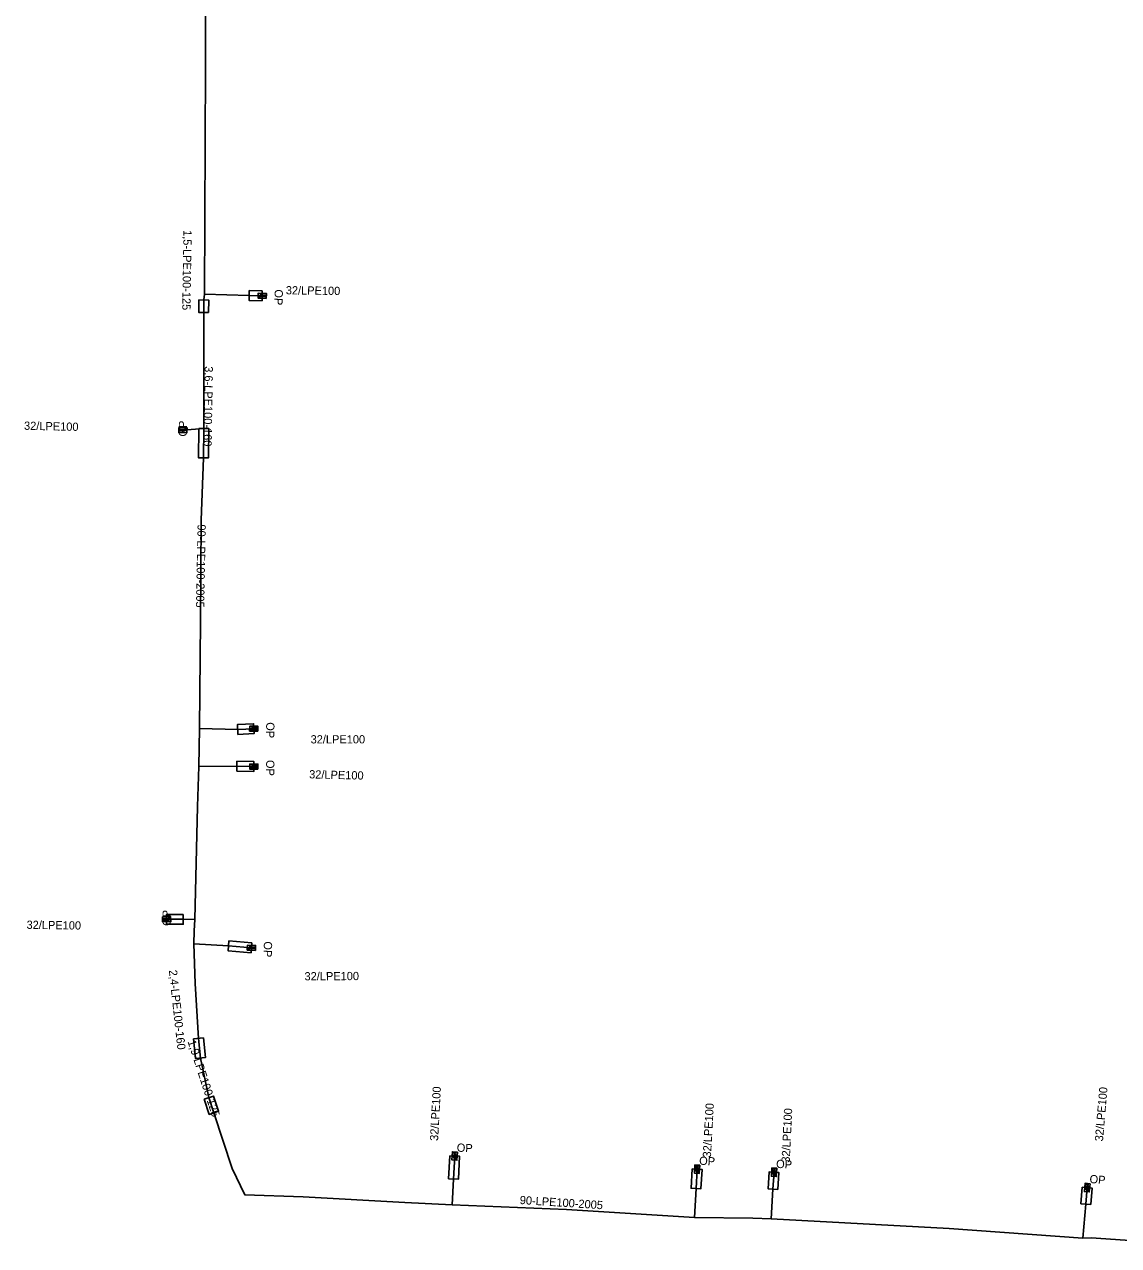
# Model space of a CAD drawing. Extents: x -762921 to -762499, y -1152946 to -1152170.
# Drawn here: x -762776.2 to -762643.3, y -1152901.4 to -1152753 of the extents above; entities that cross this region are included whole.
import ezdxf

# ---------------------------------------------------------------- set-up
doc = ezdxf.new("R2010")
doc.units = 0
for name, color, linetype in [('Vrstva 21', 7, 'Continuous'), ('Vrstva 29', 7, 'Continuous'), ('Vrstva 31', 7, 'Continuous'), ('Vrstva 32', 7, 'Continuous')]:
    doc.layers.add(name, color=color, linetype=linetype)

msp = doc.modelspace()

# ---------------------------------------------------------------- linework, layer by layer
at = {"layer": 'Vrstva 21'}
msp.add_lwpolyline([(-762754.26, -1152739.11), (-762754.22, -1152758.13), (-762754.35, -1152785.8), (-762754.43, -1152786.51), (-762754.45, -1152788.03), (-762754.42, -1152802.11), (-762754.48, -1152805.69), (-762754.74, -1152813.25), (-762754.82, -1152825.57), (-762754.96, -1152838.56), (-762755.02, -1152843.17), (-762755.19, -1152848.05), (-762755.54, -1152861.75), (-762755.6, -1152863.15), (-762755.66, -1152864.72), (-762755.5, -1152869.53), (-762755.09, -1152876.2), (-762754.83, -1152878.59), (-762753.81, -1152883.39), (-762753.21, -1152885.23), (-762751, -1152892), (-762749.45, -1152895.2), (-762742.38, -1152895.45), (-762730.02, -1152896.13), (-762724.27, -1152896.43), (-762710.39, -1152896.96), (-762694.84, -1152897.93), (-762687.76, -1152898.05), (-762685.52, -1152898.12), (-762663.91, -1152899.29), (-762647.65, -1152900.48), (-762646.67, -1152900.42), (-762633.1, -1152901.36)], dxfattribs=at)
at = {"layer": 'Vrstva 29'}
for points in [[(-762747.33, -1152785.4), (-762748.91, -1152785.37), (-762748.93, -1152786.57), (-762747.35, -1152786.6)], [(-762753.85, -1152788.04), (-762753.83, -1152786.52), (-762755.03, -1152786.5), (-762755.05, -1152788.02)], [(-762755.02, -1152802.1), (-762755.08, -1152805.68), (-762753.88, -1152805.7), (-762753.82, -1152802.12)], [(-762750.29, -1152839.28), (-762748.33, -1152839.18), (-762748.39, -1152837.98), (-762750.35, -1152838.08)], [(-762750.43, -1152843.74), (-762748.37, -1152843.78), (-762748.35, -1152842.58), (-762750.41, -1152842.54)], [(-762756.94, -1152861.13), (-762758.95, -1152861.13), (-762758.95, -1152862.33), (-762756.94, -1152862.33)], [(-762748.6, -1152864.59), (-762751.39, -1152864.36), (-762751.49, -1152865.56), (-762748.7, -1152865.79)], [(-762755.69, -1152876.26), (-762755.43, -1152878.65), (-762754.23, -1152878.52), (-762754.49, -1152876.14)], [(-762754.38, -1152883.58), (-762753.78, -1152885.42), (-762752.64, -1152885.04), (-762753.24, -1152883.2)], [(-762724.56, -1152890.45), (-762724.71, -1152893.25), (-762723.51, -1152893.31), (-762723.36, -1152890.51)], [(-762695.12, -1152892.05), (-762695.25, -1152894.4), (-762694.05, -1152894.46), (-762693.92, -1152892.11)], [(-762684.7, -1152894.53), (-762684.57, -1152892.5), (-762685.77, -1152892.42), (-762685.9, -1152894.45)], [(-762647.73, -1152894.27), (-762647.9, -1152896.27), (-762646.7, -1152896.37), (-762646.53, -1152894.37)]]:
    msp.add_lwpolyline(points, close=True, dxfattribs=at)
at = {"layer": 'Vrstva 31'}
for points in [[(-762754.35, -1152785.8), (-762748.92, -1152785.97), (-762747.34, -1152786)], [(-762754.42, -1152802.11), (-762756.98, -1152802.32)], [(-762754.96, -1152838.56), (-762750.32, -1152838.68), (-762748.36, -1152838.58)], [(-762755.02, -1152843.17), (-762750.42, -1152843.14), (-762748.36, -1152843.18)], [(-762755.54, -1152861.75), (-762756.94, -1152861.73), (-762758.95, -1152861.73)], [(-762755.66, -1152864.72), (-762751.44, -1152864.96), (-762748.65, -1152865.19)], [(-762724.27, -1152896.43), (-762724.11, -1152893.28), (-762723.96, -1152890.48)], [(-762694.84, -1152897.93), (-762694.65, -1152894.43), (-762694.52, -1152892.08)], [(-762685.52, -1152898.12), (-762685.3, -1152894.49), (-762685.17, -1152892.46)], [(-762647.65, -1152900.48), (-762647.3, -1152896.32), (-762647.13, -1152894.32)]]:
    msp.add_lwpolyline(points, dxfattribs=at)
at = {"layer": 'Vrstva 32'}
for p, q in [((-762747.536, -1152785.82), (-762747.545, -1152786.17)), ((-762747.137, -1152785.831), (-762747.146, -1152786.18)), ((-762746.941, -1152786.021), (-762747.142, -1152786.015)), ((-762746.945, -1152786.186), (-762746.936, -1152785.836)), ((-762757.375, -1152802.135), (-762757.384, -1152802.485)), ((-762757.379, -1152802.3), (-762757.179, -1152802.305)), ((-762757.183, -1152802.49), (-762757.174, -1152802.141)), ((-762756.784, -1152802.5), (-762756.776, -1152802.151)), ((-762748.558, -1152838.402), (-762748.562, -1152838.752)), ((-762748.159, -1152838.407), (-762748.163, -1152838.757)), ((-762747.96, -1152838.595), (-762748.161, -1152838.592)), ((-762747.962, -1152838.76), (-762747.958, -1152838.41)), ((-762748.56, -1152843.005), (-762748.56, -1152843.355)), ((-762748.161, -1152843.005), (-762748.161, -1152843.355)), ((-762747.96, -1152843.19), (-762748.161, -1152843.19)), ((-762747.96, -1152843.355), (-762747.96, -1152843.005)), ((-762759.356, -1152861.571), (-762759.342, -1152861.921)), ((-762759.35, -1152861.736), (-762759.149, -1152861.728)), ((-762759.141, -1152861.913), (-762759.155, -1152861.563)), ((-762758.743, -1152861.897), (-762758.757, -1152861.547)), ((-762748.846, -1152865.011), (-762748.855, -1152865.36)), ((-762748.447, -1152865.021), (-762748.456, -1152865.37)), ((-762748.255, -1152865.376), (-762748.246, -1152865.026)), ((-762748.251, -1152865.211), (-762748.452, -1152865.206)), ((-762724.124, -1152890.272), (-762723.774, -1152890.292)), ((-762723.763, -1152890.091), (-762724.113, -1152890.071)), ((-762723.928, -1152890.082), (-762723.939, -1152890.282)), ((-762724.146, -1152890.67), (-762723.797, -1152890.69)), ((-762694.321, -1152891.691), (-762694.67, -1152891.67)), ((-762694.486, -1152891.681), (-762694.498, -1152891.882)), ((-762694.707, -1152892.269), (-762694.358, -1152892.29)), ((-762694.683, -1152891.87), (-762694.333, -1152891.892)), ((-762685.355, -1152892.65), (-762685.006, -1152892.669)), ((-762685.334, -1152892.252), (-762684.984, -1152892.271)), ((-762684.973, -1152892.07), (-762685.323, -1152892.051)), ((-762685.138, -1152892.061), (-762685.149, -1152892.262)), ((-762647.322, -1152894.505), (-762646.973, -1152894.535)), ((-762647.287, -1152894.107), (-762646.939, -1152894.137)), ((-762646.922, -1152893.937), (-762647.27, -1152893.907)), ((-762647.086, -1152893.923), (-762647.103, -1152894.123))]:
    msp.add_line(p, q, dxfattribs=at)
for points in [[(-762746.848, -1152786.313), (-762747.848, -1152786.288), (-762747.833, -1152785.688), (-762746.833, -1152785.713), (-762746.848, -1152786.313)], [(-762747.545, -1152786.17), (-762747.675, -1152786.167), (-762747.716, -1152786.149), (-762747.731, -1152786.133), (-762747.744, -1152786.099), (-762747.743, -1152786.049), (-762747.728, -1152786.017), (-762747.712, -1152786.001), (-762747.67, -1152785.985), (-762747.54, -1152785.988)], [(-762747.245, -1152786.178), (-762747.238, -1152785.927), (-762747.251, -1152785.878), (-762747.281, -1152785.844), (-762747.323, -1152785.826), (-762747.352, -1152785.825), (-762747.394, -1152785.841), (-762747.424, -1152785.873), (-762747.439, -1152785.922), (-762747.446, -1152786.173)], [(-762757.472, -1152802.008), (-762756.473, -1152802.033), (-762756.488, -1152802.633), (-762757.487, -1152802.608), (-762757.472, -1152802.008)], [(-762757.075, -1152802.143), (-762757.082, -1152802.394), (-762757.069, -1152802.443), (-762757.039, -1152802.477), (-762756.997, -1152802.495), (-762756.968, -1152802.496), (-762756.926, -1152802.48), (-762756.896, -1152802.448), (-762756.881, -1152802.399), (-762756.875, -1152802.148)], [(-762756.776, -1152802.151), (-762756.646, -1152802.154), (-762756.604, -1152802.172), (-762756.589, -1152802.188), (-762756.576, -1152802.222), (-762756.578, -1152802.271), (-762756.592, -1152802.304), (-762756.608, -1152802.32), (-762756.65, -1152802.336), (-762756.78, -1152802.332)], [(-762747.864, -1152838.886), (-762748.864, -1152838.873), (-762748.856, -1152838.273), (-762747.856, -1152838.286), (-762747.864, -1152838.886)], [(-762748.562, -1152838.752), (-762748.692, -1152838.751), (-762748.734, -1152838.733), (-762748.749, -1152838.717), (-762748.762, -1152838.684), (-762748.762, -1152838.634), (-762748.747, -1152838.601), (-762748.732, -1152838.585), (-762748.69, -1152838.569), (-762748.56, -1152838.57)], [(-762748.262, -1152838.756), (-762748.259, -1152838.505), (-762748.272, -1152838.456), (-762748.303, -1152838.422), (-762748.345, -1152838.405), (-762748.374, -1152838.405), (-762748.416, -1152838.421), (-762748.445, -1152838.454), (-762748.46, -1152838.502), (-762748.463, -1152838.753)], [(-762747.86, -1152843.48), (-762748.86, -1152843.479), (-762748.86, -1152842.879), (-762747.86, -1152842.88), (-762747.86, -1152843.48)], [(-762748.56, -1152843.355), (-762748.69, -1152843.355), (-762748.732, -1152843.338), (-762748.747, -1152843.322), (-762748.761, -1152843.289), (-762748.761, -1152843.239), (-762748.747, -1152843.206), (-762748.732, -1152843.19), (-762748.69, -1152843.173), (-762748.56, -1152843.173)], [(-762748.26, -1152843.355), (-762748.26, -1152843.104), (-762748.274, -1152843.055), (-762748.305, -1152843.022), (-762748.347, -1152843.005), (-762748.376, -1152843.005), (-762748.418, -1152843.022), (-762748.447, -1152843.055), (-762748.461, -1152843.104), (-762748.461, -1152843.355)], [(-762759.461, -1152861.45), (-762758.462, -1152861.41), (-762758.438, -1152862.01), (-762759.437, -1152862.05), (-762759.461, -1152861.45)], [(-762759.056, -1152861.559), (-762759.046, -1152861.81), (-762759.03, -1152861.859), (-762758.998, -1152861.89), (-762758.956, -1152861.906), (-762758.927, -1152861.904), (-762758.885, -1152861.886), (-762758.858, -1152861.852), (-762758.846, -1152861.802), (-762758.856, -1152861.551)], [(-762758.757, -1152861.547), (-762758.627, -1152861.542), (-762758.584, -1152861.557), (-762758.569, -1152861.573), (-762758.553, -1152861.605), (-762758.551, -1152861.655), (-762758.564, -1152861.689), (-762758.578, -1152861.705), (-762758.62, -1152861.724), (-762758.749, -1152861.729)], [(-762748.158, -1152865.503), (-762749.158, -1152865.478), (-762749.142, -1152864.878), (-762748.143, -1152864.903), (-762748.158, -1152865.503)], [(-762748.555, -1152865.368), (-762748.548, -1152865.117), (-762748.561, -1152865.068), (-762748.591, -1152865.034), (-762748.633, -1152865.016), (-762748.662, -1152865.015), (-762748.704, -1152865.031), (-762748.734, -1152865.063), (-762748.749, -1152865.112), (-762748.756, -1152865.363)], [(-762748.855, -1152865.36), (-762748.985, -1152865.357), (-762749.026, -1152865.339), (-762749.041, -1152865.323), (-762749.054, -1152865.289), (-762749.053, -1152865.239), (-762749.038, -1152865.207), (-762749.022, -1152865.191), (-762748.98, -1152865.175), (-762748.85, -1152865.178)], [(-762723.633, -1152889.998), (-762723.689, -1152890.996), (-762724.288, -1152890.963), (-762724.232, -1152889.964), (-762723.633, -1152889.998)], [(-762723.78, -1152890.39), (-762724.031, -1152890.376), (-762724.08, -1152890.387), (-762724.115, -1152890.417), (-762724.134, -1152890.458), (-762724.136, -1152890.486), (-762724.121, -1152890.529), (-762724.09, -1152890.56), (-762724.042, -1152890.577), (-762723.791, -1152890.591)], [(-762723.797, -1152890.69), (-762723.804, -1152890.82), (-762723.824, -1152890.861), (-762723.84, -1152890.875), (-762723.874, -1152890.887), (-762723.924, -1152890.884), (-762723.956, -1152890.868), (-762723.971, -1152890.852), (-762723.986, -1152890.809), (-762723.979, -1152890.68)], [(-762694.19, -1152891.599), (-762694.251, -1152892.597), (-762694.85, -1152892.56), (-762694.789, -1152891.562), (-762694.19, -1152891.599)], [(-762694.339, -1152891.991), (-762694.59, -1152891.975), (-762694.64, -1152891.986), (-762694.674, -1152892.015), (-762694.694, -1152892.056), (-762694.696, -1152892.085), (-762694.681, -1152892.128), (-762694.65, -1152892.159), (-762694.602, -1152892.176), (-762694.352, -1152892.191)], [(-762694.358, -1152892.29), (-762694.366, -1152892.42), (-762694.385, -1152892.461), (-762694.402, -1152892.475), (-762694.436, -1152892.487), (-762694.486, -1152892.484), (-762694.518, -1152892.468), (-762694.533, -1152892.452), (-762694.547, -1152892.409), (-762694.539, -1152892.279)], [(-762684.843, -1152891.977), (-762684.897, -1152892.976), (-762685.496, -1152892.943), (-762685.442, -1152891.945), (-762684.843, -1152891.977)], [(-762684.989, -1152892.37), (-762685.24, -1152892.356), (-762685.29, -1152892.368), (-762685.324, -1152892.397), (-762685.344, -1152892.438), (-762685.345, -1152892.467), (-762685.33, -1152892.51), (-762685.299, -1152892.54), (-762685.251, -1152892.557), (-762685, -1152892.57)], [(-762685.006, -1152892.669), (-762685.013, -1152892.799), (-762685.032, -1152892.84), (-762685.049, -1152892.854), (-762685.082, -1152892.866), (-762685.132, -1152892.864), (-762685.164, -1152892.848), (-762685.18, -1152892.832), (-762685.194, -1152892.789), (-762685.187, -1152892.659)], [(-762646.788, -1152893.848), (-762646.874, -1152894.844), (-762647.472, -1152894.793), (-762647.386, -1152893.796), (-762646.788, -1152893.848)], [(-762646.947, -1152894.236), (-762647.197, -1152894.214), (-762647.247, -1152894.224), (-762647.283, -1152894.252), (-762647.303, -1152894.292), (-762647.306, -1152894.321), (-762647.293, -1152894.365), (-762647.262, -1152894.396), (-762647.214, -1152894.414), (-762646.964, -1152894.436)], [(-762646.973, -1152894.535), (-762646.984, -1152894.664), (-762647.005, -1152894.704), (-762647.022, -1152894.718), (-762647.056, -1152894.729), (-762647.106, -1152894.725), (-762647.137, -1152894.708), (-762647.152, -1152894.692), (-762647.165, -1152894.648), (-762647.154, -1152894.519)]]:
    msp.add_lwpolyline(points, dxfattribs=at)

# ---------------------------------------------------------------- texts
at = {"layer": 'Vrstva 21'}
for rotation, p in [(268.86528, (-762755.19, -1152813.76)), (356.35357, (-762716.08, -1152896.31))]:
    msp.add_text('90-LPE100-2005', height=1, rotation=rotation, dxfattribs=at).set_placement(p)
at = {"layer": 'Vrstva 29'}
for s, rotation, p in [('1,5-LPE100-125', 269.0883, (-762756.9, -1152778.01)), ('3,6-LPE100-160', 269.03983, (-762754.32, -1152794.55)), ('2,4-LPE100-160', 276.2086, (-762758.68, -1152867.93)), ('1,9-LPE100-125', 288.06047, (-762756.42, -1152876.57))]:
    msp.add_text(s, height=1, rotation=rotation, dxfattribs=at).set_placement(p)
at = {"layer": 'Vrstva 31'}
for rotation, p in [(359.23389, (-762744.48, -1152785.82)), (359.23389, (-762744.48, -1152785.82)), (358.7288, (-762776.28, -1152802.27)), (358.7288, (-762776.28, -1152802.27)), (0.0454, (-762741.46, -1152840.37)), (0.0454, (-762741.46, -1152840.37)), (358.62745, (-762741.65, -1152844.61)), (358.62745, (-762741.65, -1152844.61)), (359.18154, (-762775.97, -1152862.89)), (359.18154, (-762775.97, -1152862.89)), (0.30826, (-762742.2, -1152869.15)), (0.30826, (-762742.2, -1152869.15)), (86.93351, (-762725.98, -1152888.67)), (86.93351, (-762725.98, -1152888.67)), (85.14154, (-762645.22, -1152888.74)), (85.14154, (-762645.22, -1152888.74)), (86.83367, (-762692.84, -1152890.69)), (86.83367, (-762692.84, -1152890.69)), (87.25861, (-762683.27, -1152891.31)), (87.25861, (-762683.27, -1152891.31))]:
    msp.add_text('32/LPE100', height=1, rotation=rotation, dxfattribs=at).set_placement(p)
at = {"layer": 'Vrstva 32'}
for rotation, p in [(268.541, (-762745.82, -1152785.21)), (268.541, (-762745.82, -1152785.21)), (88.56507, (-762756.5, -1152803.11)), (88.56507, (-762756.5, -1152803.11)), (269.27343, (-762746.85, -1152837.79)), (269.27343, (-762746.85, -1152837.79)), (269.96321, (-762746.86, -1152842.38)), (269.96321, (-762746.86, -1152842.38)), (90, (-762758.45, -1152862.53)), (90, (-762758.45, -1152862.53)), (268.5536, (-762747.13, -1152864.4)), (268.5536, (-762747.13, -1152864.4)), (356.77092, (-762723.73, -1152889.94)), (356.77092, (-762723.73, -1152889.94)), (356.49579, (-762694.29, -1152891.53)), (356.49579, (-762694.29, -1152891.53)), (356.91391, (-762684.94, -1152891.92)), (356.91391, (-762684.94, -1152891.92)), (355.09087, (-762646.88, -1152893.75)), (355.09087, (-762646.88, -1152893.75))]:
    msp.add_text('OP', height=1, rotation=rotation, dxfattribs=at).set_placement(p)

doc.saveas('drawing.dxf')
